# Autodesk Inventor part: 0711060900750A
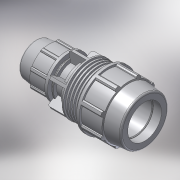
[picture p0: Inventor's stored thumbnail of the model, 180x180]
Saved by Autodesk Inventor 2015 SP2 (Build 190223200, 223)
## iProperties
Created: 2017-02
Part Number: 0711060900750A
Material: PVC-Piping
Description: PLASSON REDUCING COUPLER 90-75
Document SubType Name: Modeling
Designer: KIM
Mass: 92.6774 g
Surface Area: 199.44 cm^2
Volume: 66.1981 cm^3
Density: 1.4 g/cm^3
Appearance: Smooth - White
Author: KIM
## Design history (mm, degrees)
derived "87110.ipt"
feature "Solid1::87110.ipt"
tag "TaggingFeature1"
body "Solid1"
other parameters: "d4" = 27.5, "d5" = 47.14286, "d7" = 154, "d9" = 47.14286, "d11" = 4.71429, "d12" = 123.2, "d13" = 120 deg, "d14" = 126, "d15" = 6 deg, "d16" = 138.6, "d18" = 4.5, "d19" = 35 deg, "d20" = 17.5 deg, "d21" = 143.22, "d23" = 0, "d25" = 360 deg, "d27" = 3.08, "d42" = 72.6, "d46" = 1.8, "d52" = 47.14286, "d53" = 8 deg, "d56" = 105, "d57" = 75, "d58" = 81, "d59" = 67.5, "d60" = 120.6, "d61" = 107.2, "d62" = 41.25, "d63" = 59.4, "d64" = 120 deg, "d65" = 134, "d68" = 23.57143, "d74" = 124.62, "d75" = 35 deg, "d76" = 17.5 deg, "d78" = 0, "d80" = 360 deg, "d85" = 2.68, "d88" = 1.5, "d93" = 134, "d94" = 107.8, "d98" = 8.93333, "d99" = 0, "d100" = 6.16, "d102" = 360 deg, "d104" = 2, "d106" = 0, "d107" = 8.93333, "d108" = 0, "d109" = 8.93333, "d110" = 0, "d111" = 3.21667, "d112" = 3.21667, "d113" = 3.21667, "d114" = 3.49714, "d116" = 3.49714, "d119" = 6.99429, "d125" = 135.828, "E_" = 154, "d_1" = 75, "E_1" = 134, "l_1" = 134, "d96" = 9.65, "d115" = 34.97143
